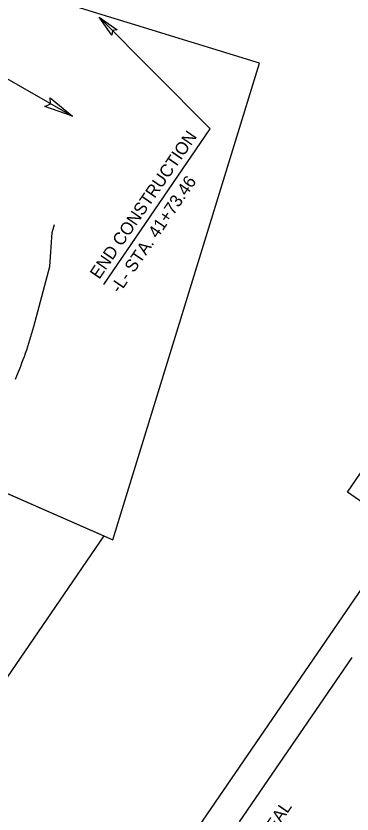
# Model space of a CAD drawing. Extents: x 1638787 to 1643250, y 391480 to 396306.
# Drawn here: x 1642055 to 1642460, y 394319 to 395279 of the extents above; entities that cross this region are included whole.
import ezdxf

# ---------------------------------------------------------------- set-up
doc = ezdxf.new("R2010")
doc.units = 0
for name, color, linetype in [('Old_Level_1', 7, 'Continuous'), ('Prop 8 In Water Line (St)', 7, 'Continuous'), ('Prop Terminator CELL', 7, 'Continuous'), ('Sheet Plan Layout CELL', 7, 'Continuous'), ('UC Title Plan Sheet 34 CELL', 7, 'Continuous')]:
    doc.layers.add(name, color=color, linetype=linetype)

msp = doc.modelspace()

# ---------------------------------------------------------------- linework, layer by layer
at = {"layer": 'Old_Level_1'}
for p, q in [((1641860.25, 395308.72), (1642122.83, 395158.25)), ((1642155.08, 395277.42), (1642288.74, 395142.96)), ((1642160.45, 394955.89), (1642288.74, 395142.96))]:
    msp.add_line(p, q, dxfattribs=at)
at = {"layer": 'Prop 8 In Water Line (St)'}
for p, q in [((1642098.54, 395018.38), (1642101.15, 395028.03)), ((1642095.72, 394977.32), (1642098.54, 395018.38)), ((1642076.22, 394905.36), (1642095.72, 394977.32))]:
    msp.add_line(p, q, dxfattribs=at)
msp.add_arc((1641632.24, 395025.73), 460, 336.46564, 344.83067, dxfattribs=at)
at = {"layer": 'Prop Terminator CELL'}
for points in [[(1642170.19, 395255.89), (1642155.08, 395277.42), (1642176.72, 395262.18), (1642171.12, 395261.28)], [(1642095.8, 395180.59), (1642122.83, 395158.25), (1642089.62, 395170.19), (1642096.51, 395173.33)]]:
    msp.add_lwpolyline(points, close=True, dxfattribs=at)
at = {"layer": 'Sheet Plan Layout CELL'}
for points in [[(1642171.61, 394648.64), (1642347.99, 395222.13), (1641946.55, 395345.6), (1641784.33, 394818.15)], [(1641858.66, 394213.18), (1641512.28, 394450.71), (1641768.89, 394824.91), (1642160.59, 394653.47)]]:
    msp.add_lwpolyline(points, close=True, dxfattribs=at)
at = {"layer": 'UC Title Plan Sheet 34 CELL'}
for p, q in [((1640853.78, 392231.25), (1642781.17, 395041.88)), ((1642323.93, 394309.21), (1642459.69, 394506.97))]:
    msp.add_line(p, q, dxfattribs=at)
msp.add_lwpolyline([(1642500.58, 394673.89), (1642454.1, 394705.76), (1642717.35, 395089.72), (1642763.86, 395057.82)], close=True, dxfattribs=at)

# ---------------------------------------------------------------- texts
at = {"layer": 'Old_Level_1'}
for s, p in [('END CONSTRUCTION', (1642155.02, 394961.22)), ('-L- STA. 41+73.46', (1642179.76, 394944.26))]:
    msp.add_text(s, height=15, rotation=55.55969, dxfattribs=at).set_placement(p)
at = {"layer": 'UC Title Plan Sheet 34 CELL'}
msp.add_text('SEAL ', height=14.836, rotation=55.54546, dxfattribs=at).set_placement((1642359.14, 394285.82))

doc.saveas('drawing.dxf')
